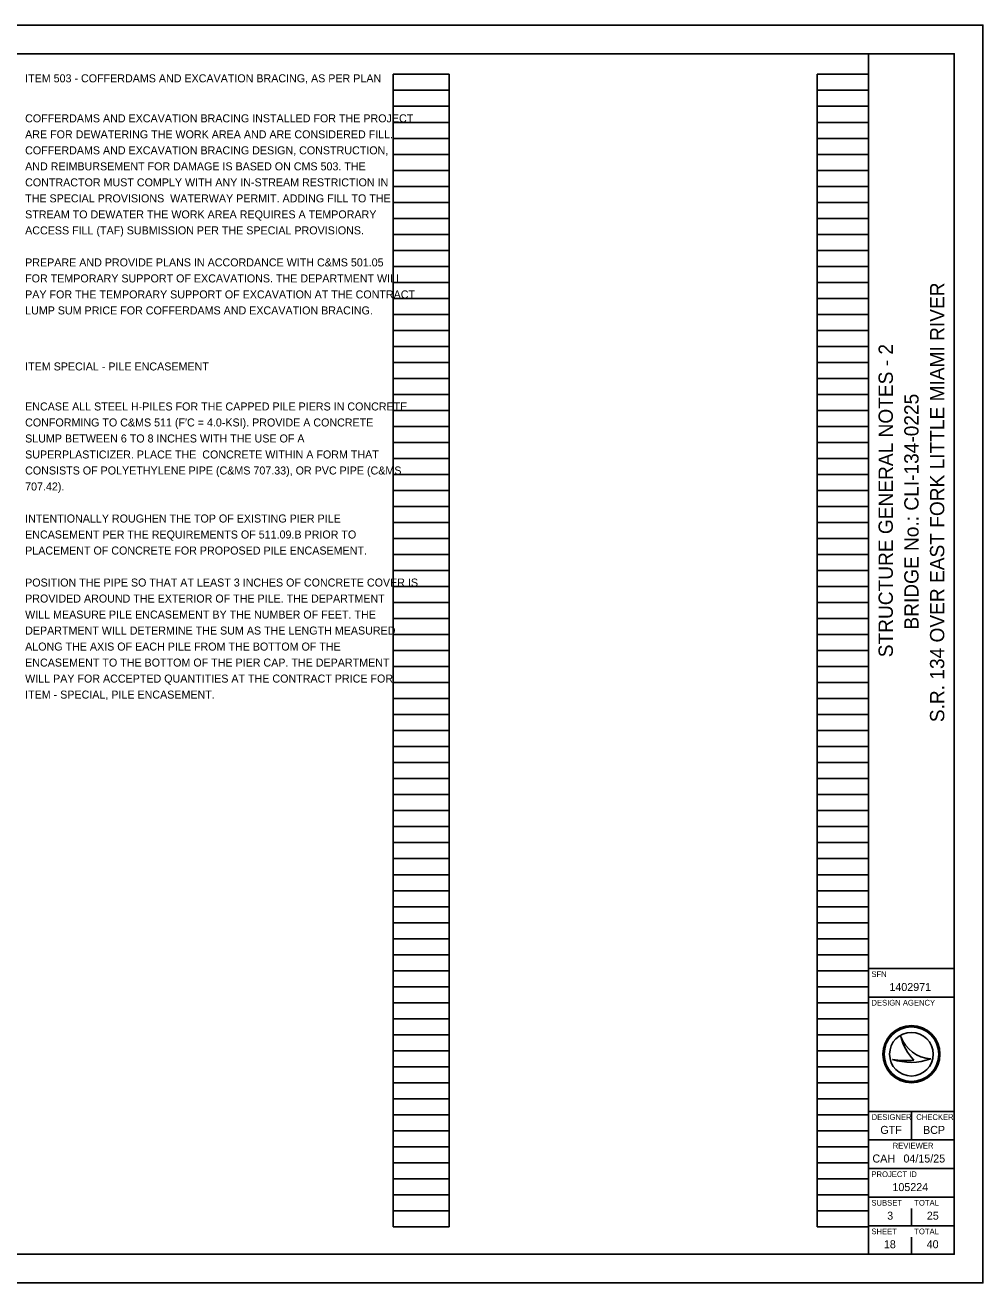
# Model space of a CAD drawing. Extents: x 0 to 55.2, y -1 to 22.
# Drawn here: x 17.24 to 34, y 0 to 22 of the extents above; entities that cross this region are included whole.
import ezdxf

# ---------------------------------------------------------------- set-up
doc = ezdxf.new("R2010")
doc.units = 0
for name, color, linetype in [('SH_Border', 7, 'Continuous'), ('SH_Cut_Line', 7, 'Continuous'), ('SH_Data', 7, 'Continuous'), ('SH_Text', 7, 'Continuous')]:
    doc.layers.add(name, color=color, linetype=linetype)

msp = doc.modelspace()

# ---------------------------------------------------------------- linework, layer by layer
at = {"layer": 'SH_Border'}
for p, q in [((32, 0.5), (32, 21.5)), ((32, 5.5), (33.5, 5.5)), ((32, 5), (33.5, 5)), ((32, 3), (33.5, 3)), ((32.75, 3), (32.75, 2.5)), ((32, 2.5), (33.5, 2.5)), ((32, 2), (33.5, 2)), ((32, 1.5), (33.5, 1.5)), ((32, 1), (33.5, 1))]:
    msp.add_line(p, q, dxfattribs=at)
msp.add_lwpolyline([(1.5, 21.5), (33.5, 21.5), (33.5, 0.5), (1.5, 0.5)], close=True, dxfattribs=at)
at = {"layer": 'SH_Cut_Line'}
msp.add_lwpolyline([(0, 0), (34, 0), (34, 22), (0, 22)], close=True, dxfattribs=at)
at = {"layer": 'SH_Data'}
for p, q in [((23.68, 0.98), (23.68, 21.14)), ((23.68, 21.14), (24.66, 21.14)), ((24.66, 0.98), (24.66, 21.14)), ((31.1, 0.98), (31.1, 21.14)), ((31.1, 21.14), (32, 21.14)), ((32, 0.98), (32, 21.14)), ((23.68, 20.86), (24.66, 20.86)), ((31.1, 20.86), (32, 20.86)), ((23.68, 20.58), (24.66, 20.58)), ((31.1, 20.58), (32, 20.58)), ((23.68, 20.3), (24.66, 20.3)), ((31.1, 20.3), (32, 20.3)), ((23.68, 20.02), (24.66, 20.02)), ((31.1, 20.02), (32, 20.02)), ((23.68, 19.74), (24.66, 19.74)), ((31.1, 19.74), (32, 19.74)), ((23.68, 19.46), (24.66, 19.46)), ((31.1, 19.46), (32, 19.46)), ((23.68, 19.18), (24.66, 19.18)), ((31.1, 19.18), (32, 19.18)), ((23.68, 18.9), (24.66, 18.9)), ((31.1, 18.9), (32, 18.9)), ((23.68, 18.62), (24.66, 18.62)), ((31.1, 18.62), (32, 18.62)), ((23.68, 18.34), (24.66, 18.34)), ((31.1, 18.34), (32, 18.34)), ((23.68, 18.06), (24.66, 18.06)), ((31.1, 18.06), (32, 18.06)), ((23.68, 17.78), (24.66, 17.78)), ((31.1, 17.78), (32, 17.78)), ((23.68, 17.5), (24.66, 17.5)), ((31.1, 17.5), (32, 17.5)), ((23.68, 17.22), (24.66, 17.22)), ((31.1, 17.22), (32, 17.22)), ((23.68, 16.94), (24.66, 16.94)), ((31.1, 16.94), (32, 16.94)), ((23.68, 16.66), (24.66, 16.66)), ((31.1, 16.66), (32, 16.66)), ((23.68, 16.38), (24.66, 16.38)), ((31.1, 16.38), (32, 16.38)), ((23.68, 16.1), (24.66, 16.1)), ((31.1, 16.1), (32, 16.1)), ((23.68, 15.82), (24.66, 15.82)), ((31.1, 15.82), (32, 15.82)), ((23.68, 15.54), (24.66, 15.54)), ((31.1, 15.54), (32, 15.54)), ((23.68, 15.26), (24.66, 15.26)), ((31.1, 15.26), (32, 15.26)), ((23.68, 14.98), (24.66, 14.98)), ((31.1, 14.98), (32, 14.98)), ((23.68, 14.7), (24.66, 14.7)), ((31.1, 14.7), (32, 14.7)), ((23.68, 14.42), (24.66, 14.42)), ((31.1, 14.42), (32, 14.42)), ((23.68, 14.14), (24.66, 14.14)), ((31.1, 14.14), (32, 14.14)), ((23.68, 13.86), (24.66, 13.86)), ((31.1, 13.86), (32, 13.86)), ((23.68, 13.58), (24.66, 13.58)), ((31.1, 13.58), (32, 13.58)), ((23.68, 13.3), (24.66, 13.3)), ((31.1, 13.3), (32, 13.3)), ((23.68, 13.02), (24.66, 13.02)), ((31.1, 13.02), (32, 13.02)), ((23.68, 12.74), (24.66, 12.74)), ((31.1, 12.74), (32, 12.74)), ((23.68, 12.46), (24.66, 12.46)), ((31.1, 12.46), (32, 12.46)), ((23.68, 12.18), (24.66, 12.18)), ((31.1, 12.18), (32, 12.18)), ((23.68, 11.9), (24.66, 11.9)), ((31.1, 11.9), (32, 11.9)), ((23.68, 11.62), (24.66, 11.62)), ((31.1, 11.62), (32, 11.62)), ((23.68, 11.34), (24.66, 11.34)), ((31.1, 11.34), (32, 11.34)), ((23.68, 11.06), (24.66, 11.06)), ((31.1, 11.06), (32, 11.06)), ((23.68, 10.78), (24.66, 10.78)), ((31.1, 10.78), (32, 10.78)), ((23.68, 10.5), (24.66, 10.5)), ((31.1, 10.5), (32, 10.5)), ((23.68, 10.22), (24.66, 10.22)), ((31.1, 10.22), (32, 10.22)), ((23.68, 9.94), (24.66, 9.94)), ((31.1, 9.94), (32, 9.94)), ((23.68, 9.66), (24.66, 9.66)), ((31.1, 9.66), (32, 9.66)), ((23.68, 9.38), (24.66, 9.38)), ((31.1, 9.38), (32, 9.38)), ((23.68, 9.1), (24.66, 9.1)), ((31.1, 9.1), (32, 9.1)), ((23.68, 8.82), (24.66, 8.82)), ((31.1, 8.82), (32, 8.82)), ((23.68, 8.54), (24.66, 8.54)), ((31.1, 8.54), (32, 8.54)), ((23.68, 8.26), (24.66, 8.26)), ((31.1, 8.26), (32, 8.26)), ((23.68, 7.98), (24.66, 7.98)), ((31.1, 7.98), (32, 7.98)), ((23.68, 7.7), (24.66, 7.7)), ((31.1, 7.7), (32, 7.7)), ((23.68, 7.42), (24.66, 7.42)), ((31.1, 7.42), (32, 7.42)), ((23.68, 7.14), (24.66, 7.14)), ((31.1, 7.14), (32, 7.14)), ((23.68, 6.86), (24.66, 6.86)), ((31.1, 6.86), (32, 6.86)), ((23.68, 6.58), (24.66, 6.58)), ((31.1, 6.58), (32, 6.58)), ((23.68, 6.3), (24.66, 6.3)), ((31.1, 6.3), (32, 6.3)), ((23.68, 6.02), (24.66, 6.02)), ((31.1, 6.02), (32, 6.02)), ((23.68, 5.74), (24.66, 5.74)), ((31.1, 5.74), (32, 5.74)), ((23.68, 5.46), (24.66, 5.46)), ((31.1, 5.46), (32, 5.46)), ((23.68, 5.18), (24.66, 5.18)), ((31.1, 5.18), (32, 5.18)), ((23.68, 4.9), (24.66, 4.9)), ((31.1, 4.9), (32, 4.9)), ((23.68, 4.62), (24.66, 4.62)), ((31.1, 4.62), (32, 4.62)), ((23.68, 4.34), (24.66, 4.34)), ((31.1, 4.34), (32, 4.34)), ((32.567, 4.31), (32.567, 4.31)), ((23.68, 4.06), (24.66, 4.06)), ((31.1, 4.06), (32, 4.06)), ((32.75, 4), (32.75, 4)), ((23.68, 3.78), (24.66, 3.78)), ((31.1, 3.78), (32, 3.78)), ((32.417, 3.91), (32.417, 3.91)), ((33.087, 3.919), (33.087, 3.919)), ((23.68, 3.5), (24.66, 3.5)), ((31.1, 3.5), (32, 3.5)), ((23.68, 3.22), (24.66, 3.22)), ((31.1, 3.22), (32, 3.22)), ((23.68, 2.94), (24.66, 2.94)), ((31.1, 2.94), (32, 2.94)), ((23.68, 2.66), (24.66, 2.66)), ((31.1, 2.66), (32, 2.66)), ((23.68, 2.38), (24.66, 2.38)), ((31.1, 2.38), (32, 2.38)), ((23.68, 2.1), (24.66, 2.1)), ((31.1, 2.1), (32, 2.1)), ((23.68, 1.82), (24.66, 1.82)), ((31.1, 1.82), (32, 1.82)), ((23.68, 1.54), (24.66, 1.54)), ((31.1, 1.54), (32, 1.54)), ((23.68, 1.26), (24.66, 1.26)), ((31.1, 1.26), (32, 1.26)), ((32.75, 1), (32.75, 1.3)), ((23.68, 0.98), (24.66, 0.98)), ((31.1, 0.98), (32, 0.98)), ((32.375, 0.675), (32.375, 0.675)), ((32.75, 0.5), (32.75, 0.8))]:
    msp.add_line(p, q, dxfattribs=at)
for radius in [0.5, 0.477, 0.477, 0.382]:
    msp.add_circle((32.75, 4), radius, dxfattribs=at)
for centre, radius, start, end in [((33.116, 4.498), 0.58, 198.9257, 198.9319), ((33.347, 4.47), 0.796, 191.6379, 191.6421), ((33.116, 4.498), 0.58, 198.9319, 267.1657), ((33.347, 4.47), 0.796, 191.6421, 226.0947), ((32.739, 4.87), 1.013, 251.4576, 290.0832), ((32.648, 5.154), 1.266, 259.4964, 259.4995), ((32.739, 4.87), 1.013, 251.4527, 251.4576), ((32.648, 5.154), 1.266, 259.4995, 276.6672)]:
    msp.add_arc(centre, radius, start, end, dxfattribs=at)

# ---------------------------------------------------------------- texts
for s, p in [('S.R. 134 OVER EAST FORK LITTLE MIAMI RIVER', (33.325, 9.808)), ('STRUCTURE GENERAL NOTES - 2', (32.425, 10.943)), ('BRIDGE No.: CLI-134-0225', (32.875, 11.427))]:
    msp.add_text(s, height=0.25, rotation=90, dxfattribs=at).set_placement(p)
for s, height, p in [('SFN', 0.1, (32.05, 5.35)), ('1402971', 0.14, (32.365, 5.105)), ('DESIGN AGENCY', 0.1, (32.05, 4.85)), ('DESIGNER', 0.1, (32.054, 2.85)), ('CHECKER', 0.1, (32.835, 2.85)), ('GTF', 0.14, (32.206, 2.605)), ('BCP', 0.14, (32.954, 2.605)), ('REVIEWER', 0.1, (32.422, 2.35)), ('CAH', 0.14, (32.068, 2.105)), ('04/15/25', 0.14, (32.611, 2.105)), ('PROJECT ID', 0.1, (32.05, 1.85)), ('105224', 0.14, (32.418, 1.605)), ('SUBSET', 0.1, (32.05, 1.35)), ('TOTAL', 0.1, (32.8, 1.35)), ('3', 0.14, (32.326, 1.105)), ('25', 0.14, (33.02, 1.105)), ('SHEET', 0.1, (32.05, 0.85)), ('TOTAL', 0.1, (32.8, 0.85)), ('18', 0.14, (32.268, 0.605)), ('40', 0.14, (33.017, 0.605))]:
    msp.add_text(s, height=height, dxfattribs=at).set_placement(p)
at = {"layer": 'SH_Text'}
for s, p in [('ITEM 503 - COFFERDAMS AND EXCAVATION BRACING, AS PER PLAN', (17.24, 21)), ('COFFERDAMS AND EXCAVATION BRACING INSTALLED FOR THE PROJECT ', (17.24, 20.3)), ('ARE FOR DEWATERING THE WORK AREA AND ARE CONSIDERED FILL. ', (17.24, 20.02)), ('COFFERDAMS AND EXCAVATION BRACING DESIGN, CONSTRUCTION, ', (17.24, 19.74)), ('AND REIMBURSEMENT FOR DAMAGE IS BASED ON CMS 503. THE ', (17.24, 19.46)), ('CONTRACTOR MUST COMPLY WITH ANY IN-STREAM RESTRICTION IN ', (17.24, 19.18)), ('THE SPECIAL PROVISIONS  WATERWAY PERMIT. ADDING FILL TO THE ', (17.24, 18.9)), ('STREAM TO DEWATER THE WORK AREA REQUIRES A TEMPORARY ', (17.24, 18.62)), ('ACCESS FILL (TAF) SUBMISSION PER THE SPECIAL PROVISIONS.', (17.24, 18.34)), ('PREPARE AND PROVIDE PLANS IN ACCORDANCE WITH C&MS 501.05 ', (17.24, 17.78)), ('FOR TEMPORARY SUPPORT OF EXCAVATIONS. THE DEPARTMENT WILL ', (17.24, 17.5)), ('PAY FOR THE TEMPORARY SUPPORT OF EXCAVATION AT THE CONTRACT ', (17.24, 17.22)), ('LUMP SUM PRICE FOR COFFERDAMS AND EXCAVATION BRACING. ', (17.24, 16.94)), ('ITEM SPECIAL - PILE ENCASEMENT', (17.24, 15.96)), ('ENCASE ALL STEEL H-PILES FOR THE CAPPED PILE PIERS IN CONCRETE ', (17.24, 15.26)), ('CONFORMING TO C&MS 511 (F′C = 4.0-KSI). PROVIDE A CONCRETE ', (17.24, 14.98)), ('SLUMP BETWEEN 6 TO 8 INCHES WITH THE USE OF A ', (17.24, 14.7)), ('SUPERPLASTICIZER. PLACE THE  CONCRETE WITHIN A FORM THAT ', (17.24, 14.42)), ('CONSISTS OF POLYETHYLENE PIPE (C&MS 707.33), OR PVC PIPE (C&MS ', (17.24, 14.14)), ('707.42). ', (17.24, 13.86)), ('INTENTIONALLY ROUGHEN THE TOP OF EXISTING PIER PILE ', (17.24, 13.3)), ('ENCASEMENT PER THE REQUIREMENTS OF 511.09.B PRIOR TO ', (17.24, 13.02)), ('PLACEMENT OF CONCRETE FOR PROPOSED PILE ENCASEMENT.', (17.24, 12.74)), ('POSITION THE PIPE SO THAT AT LEAST 3 INCHES OF CONCRETE COVER IS ', (17.24, 12.18)), ('PROVIDED AROUND THE EXTERIOR OF THE PILE. THE DEPARTMENT ', (17.24, 11.9)), ('WILL MEASURE PILE ENCASEMENT BY THE NUMBER OF FEET. THE ', (17.24, 11.62)), ('DEPARTMENT WILL DETERMINE THE SUM AS THE LENGTH MEASURED ', (17.24, 11.34)), ('ALONG THE AXIS OF EACH PILE FROM THE BOTTOM OF THE ', (17.24, 11.06)), ('ENCASEMENT TO THE BOTTOM OF THE PIER CAP. THE DEPARTMENT ', (17.24, 10.78)), ('WILL PAY FOR ACCEPTED QUANTITIES AT THE CONTRACT PRICE FOR ', (17.24, 10.5)), ('ITEM - SPECIAL, PILE ENCASEMENT.', (17.24, 10.22))]:
    msp.add_text(s, height=0.14, dxfattribs=at).set_placement(p)

doc.saveas('drawing.dxf')
